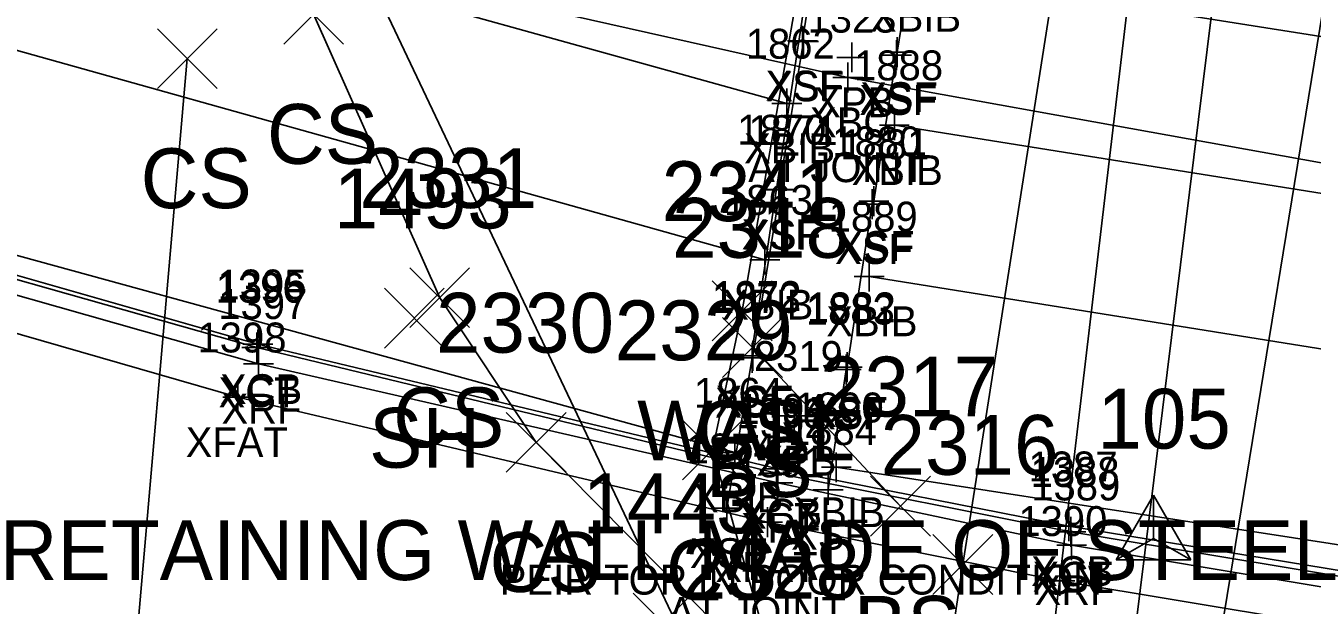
# Model space of a CAD drawing. Extents: x 1761340 to 1763889, y 696770 to 706023.
# Drawn here: x 1761614.72 to 1761657.73, y 700833.39 to 700852.76 of the extents above; entities that cross this region are included whole.
import ezdxf

# ---------------------------------------------------------------- set-up
doc = ezdxf.new("R2010")
doc.units = 0
for name, color, linetype in [('B_A', 7, 'Continuous'), ('B_C', 7, 'Continuous'), ('B_I', 7, 'Continuous'), ('B_TIC', 7, 'Continuous'), ('BB', 7, 'Continuous'), ('BDC', 7, 'Continuous'), ('BDEFAULT', 7, 'Continuous'), ('BELB', 7, 'Continuous'), ('BF', 7, 'Continuous'), ('BR', 7, 'Continuous'), ('C_I', 7, 'Continuous'), ('CPSM', 7, 'Continuous'), ('DCP', 7, 'Continuous'), ('L_A', 7, 'Continuous'), ('L_C', 7, 'Continuous'), ('L_I', 7, 'Continuous'), ('L_TIC', 7, 'Continuous'), ('LELB', 7, 'Continuous'), ('LW', 7, 'Continuous'), ('RDP', 7, 'Continuous')]:
    doc.layers.add(name, color=color, linetype=linetype)

msp = doc.modelspace()

# ---------------------------------------------------------------- linework, layer by layer
at = {"layer": 'B_TIC'}
for p, q in [((1761640.691, 700852.26), (1761640.767, 700852.26)), ((1761640.721, 700852.234), (1761640.796, 700852.234)), ((1761643.857, 700851.874), (1761643.933, 700851.874)), ((1761642.34, 700851.704), (1761642.416, 700851.704)), ((1761643.83, 700851.779), (1761643.905, 700851.779)), ((1761642.201, 700851.032), (1761642.277, 700851.032)), ((1761640.164, 700850.159), (1761640.24, 700850.159)), ((1761643.761, 700849.435), (1761643.836, 700849.435)), ((1761639.896, 700847.284), (1761639.971, 700847.284)), ((1761639.948, 700847.27), (1761640.024, 700847.27)), ((1761643.018, 700846.796), (1761643.093, 700846.796)), ((1761643.073, 700846.895), (1761643.148, 700846.895)), ((1761639.434, 700844.939), (1761639.509, 700844.939)), ((1761642.915, 700844.38), (1761642.991, 700844.38)), ((1761622.448, 700842.003), (1761622.523, 700842.003)), ((1761622.481, 700842.11), (1761622.556, 700842.11)), ((1761639.007, 700841.662), (1761639.083, 700841.662)), ((1761639.024, 700841.723), (1761639.1, 700841.723)), ((1761622.508, 700841.455), (1761622.583, 700841.455)), ((1761642.146, 700841.272), (1761642.221, 700841.272)), ((1761642.181, 700841.346), (1761642.257, 700841.346)), ((1761621.814, 700840.338), (1761621.89, 700840.338)), ((1761640.414, 700839.718), (1761640.489, 700839.718)), ((1761638.43, 700838.488), (1761638.505, 700838.488)), ((1761639.826, 700837.803), (1761639.901, 700837.803)), ((1761639.863, 700837.948), (1761639.938, 700837.948)), ((1761641.82, 700837.998), (1761641.896, 700837.998)), ((1761639.869, 700837.475), (1761639.945, 700837.475)), ((1761641.548, 700837.242), (1761641.624, 700837.242)), ((1761638.163, 700836.627), (1761638.238, 700836.627)), ((1761639.522, 700836.163), (1761639.598, 700836.163)), ((1761649.592, 700836.026), (1761649.667, 700836.026)), ((1761649.66, 700835.839), (1761649.736, 700835.839)), ((1761649.686, 700835.39), (1761649.762, 700835.39)), ((1761649.296, 700834.2), (1761649.371, 700834.2))]:
    msp.add_line(p, q, dxfattribs=at)
for points in [[(1761640.688, 700851.76), (1761640.688, 700852.76)], [(1761640.717, 700851.734), (1761640.717, 700852.734)], [(1761640.188, 700852.26), (1761641.188, 700852.26)], [(1761640.217, 700852.234), (1761641.217, 700852.234)], [(1761643.826, 700851.279), (1761643.826, 700852.279)], [(1761643.854, 700851.374), (1761643.854, 700852.374)], [(1761642.337, 700851.204), (1761642.337, 700852.204)], [(1761643.354, 700851.874), (1761644.354, 700851.874)], [(1761641.837, 700851.704), (1761642.837, 700851.704)], [(1761642.198, 700850.532), (1761642.198, 700851.532)], [(1761643.326, 700851.779), (1761644.326, 700851.779)], [(1761641.698, 700851.032), (1761642.698, 700851.032)], [(1761640.161, 700849.659), (1761640.161, 700850.659)], [(1761639.661, 700850.159), (1761640.661, 700850.159)], [(1761643.757, 700848.935), (1761643.757, 700849.935)], [(1761643.257, 700849.435), (1761644.257, 700849.435)], [(1761639.892, 700846.784), (1761639.892, 700847.784)], [(1761639.945, 700846.77), (1761639.945, 700847.77)], [(1761639.392, 700847.284), (1761640.392, 700847.284)], [(1761639.445, 700847.27), (1761640.445, 700847.27)], [(1761643.014, 700846.296), (1761643.014, 700847.296)], [(1761643.069, 700846.395), (1761643.069, 700847.395)], [(1761642.514, 700846.796), (1761643.514, 700846.796)], [(1761642.569, 700846.895), (1761643.569, 700846.895)], [(1761639.43, 700844.439), (1761639.43, 700845.439)], [(1761638.93, 700844.939), (1761639.93, 700844.939)], [(1761642.912, 700843.88), (1761642.912, 700844.88)], [(1761642.412, 700844.38), (1761643.412, 700844.38)], [(1761622.444, 700841.503), (1761622.444, 700842.503)], [(1761622.478, 700841.61), (1761622.478, 700842.61)], [(1761621.944, 700842.003), (1761622.944, 700842.003)], [(1761621.978, 700842.11), (1761622.978, 700842.11)], [(1761622.504, 700840.955), (1761622.504, 700841.955)], [(1761639.004, 700841.162), (1761639.004, 700842.162)], [(1761639.021, 700841.223), (1761639.021, 700842.223)], [(1761638.504, 700841.662), (1761639.504, 700841.662)], [(1761638.521, 700841.723), (1761639.521, 700841.723)], [(1761642.142, 700840.772), (1761642.142, 700841.772)], [(1761642.178, 700840.846), (1761642.178, 700841.846)], [(1761622.004, 700841.455), (1761623.004, 700841.455)], [(1761641.642, 700841.272), (1761642.642, 700841.272)], [(1761641.678, 700841.346), (1761642.678, 700841.346)], [(1761621.811, 700839.838), (1761621.811, 700840.838)], [(1761621.311, 700840.338), (1761622.311, 700840.338)], [(1761640.41, 700839.218), (1761640.41, 700840.218)], [(1761639.91, 700839.718), (1761640.91, 700839.718)], [(1761638.426, 700837.988), (1761638.426, 700838.988)], [(1761637.926, 700838.488), (1761638.926, 700838.488)], [(1761641.817, 700837.498), (1761641.817, 700838.498)], [(1761639.822, 700837.303), (1761639.822, 700838.303)], [(1761639.859, 700837.448), (1761639.859, 700838.448)], [(1761639.322, 700837.803), (1761640.322, 700837.803)], [(1761639.359, 700837.948), (1761640.359, 700837.948)], [(1761639.866, 700836.975), (1761639.866, 700837.975)], [(1761641.317, 700837.998), (1761642.317, 700837.998)], [(1761641.545, 700836.742), (1761641.545, 700837.742)], [(1761639.366, 700837.475), (1761640.366, 700837.475)], [(1761641.045, 700837.242), (1761642.045, 700837.242)], [(1761638.159, 700836.127), (1761638.159, 700837.127)], [(1761637.659, 700836.627), (1761638.659, 700836.627)], [(1761639.519, 700835.663), (1761639.519, 700836.663)], [(1761649.588, 700835.526), (1761649.588, 700836.526)], [(1761649.657, 700835.339), (1761649.657, 700836.339)], [(1761639.019, 700836.163), (1761640.019, 700836.163)], [(1761649.088, 700836.026), (1761650.088, 700836.026)], [(1761649.683, 700834.89), (1761649.683, 700835.89)], [(1761649.157, 700835.839), (1761650.157, 700835.839)], [(1761649.183, 700835.39), (1761650.183, 700835.39)], [(1761649.292, 700833.7), (1761649.292, 700834.7)], [(1761648.792, 700834.2), (1761649.792, 700834.2)]]:
    msp.add_lwpolyline(points, dxfattribs=at)
at = {"layer": 'BB'}
for points in [[(1761601.935, 700860.779), (1761640.161, 700850.159)], [(1761601.147, 700855.664), (1761639.43, 700844.939)], [(1761644.371, 700854.559), (1761682.392, 700848.561)], [(1761643.757, 700849.435), (1761681.627, 700843.391)], [(1761600.182, 700848.994), (1761638.426, 700838.488)], [(1761642.912, 700844.38), (1761681.017, 700838.268)], [(1761641.817, 700837.998), (1761679.884, 700832.117)]]:
    msp.add_lwpolyline(points, dxfattribs=at)
at = {"layer": 'BDC'}
for points in [[(1761724.868, 700826.95), (1761724.871, 700828.587), (1761705.949, 700829.474), (1761692.314, 700830.32), (1761682.204, 700831.236), (1761665.465, 700833.226), (1761649.657, 700835.839), (1761639.822, 700837.803), (1761622.444, 700842.003), (1761607.253, 700846.305), (1761598.594, 700848.947), (1761598.241, 700847.438)], [(1761725.044, 700828.858), (1761705.996, 700829.643), (1761692.291, 700830.53), (1761682.242, 700831.437), (1761665.497, 700833.418), (1761649.588, 700836.026), (1761639.859, 700837.948), (1761622.478, 700842.11), (1761607.258, 700846.457), (1761598.593, 700849.162)]]:
    msp.add_lwpolyline(points, dxfattribs=at)
at = {"layer": 'BDEFAULT'}
for points in [[(1761642.878, 700866.943), (1761641.572, 700857.817), (1761641.546, 700857.814), (1761640.688, 700852.26), (1761640.717, 700852.234), (1761639.892, 700847.284), (1761639.945, 700847.27), (1761639.021, 700841.723), (1761639.004, 700841.662), (1761638.159, 700836.627)], [(1761645.899, 700864.681), (1761644.76, 700857.46), (1761644.746, 700857.382), (1761643.854, 700851.874), (1761643.826, 700851.779), (1761643.069, 700846.895), (1761643.014, 700846.796), (1761642.178, 700841.346), (1761642.142, 700841.272), (1761641.545, 700837.242)]]:
    msp.add_lwpolyline(points, dxfattribs=at)
at = {"layer": 'BELB'}
msp.add_lwpolyline([(1761601.149, 700861.879), (1761622.312, 700855.499), (1761642.198, 700851.032), (1761664.959, 700846.932), (1761684.404, 700844.626), (1761702.463, 700842.89), (1761719.736, 700841.994), (1761727.361, 700840.892)], dxfattribs=at)
at = {"layer": 'BF'}
msp.add_lwpolyline([(1761724.868, 700826.95), (1761706.242, 700827.778), (1761692.328, 700828.536), (1761682.079, 700829.49), (1761665.583, 700831.495), (1761649.292, 700834.2), (1761639.519, 700836.163), (1761621.811, 700840.338), (1761606.756, 700844.682), (1761598.241, 700847.438)], dxfattribs=at)
at = {"layer": 'BR'}
msp.add_lwpolyline([(1761724.372, 700828.339), (1761706.015, 700828.859), (1761692.389, 700829.783), (1761682.17, 700830.837), (1761665.431, 700832.762), (1761649.683, 700835.39), (1761639.866, 700837.475), (1761622.504, 700841.455), (1761607.196, 700845.805), (1761599.069, 700848.455)], dxfattribs=at)
at = {"layer": 'CPSM'}
for p, q in [((1761651.166, 700834.901), (1761652.416, 700837.066)), ((1761653.666, 700834.901), (1761652.416, 700837.066)), ((1761652.416, 700835.623), (1761652.416, 700837.066)), ((1761651.166, 700834.901), (1761652.416, 700835.623)), ((1761652.416, 700835.623), (1761652.416, 700835.623)), ((1761652.416, 700835.623), (1761653.666, 700834.901)), ((1761651.166, 700834.901), (1761653.666, 700834.901))]:
    msp.add_line(p, q, dxfattribs=at)
at = {"layer": 'DCP'}
msp.add_lwpolyline([(1761640.818, 700823.61), (1761622.01, 700863.245)], dxfattribs=at)
at = {"layer": 'L_TIC'}
for points in [[(1761623.344, 700852.144), (1761625.344, 700854.144)], [(1761625.344, 700852.144), (1761623.344, 700854.144)], [(1761619.121, 700850.662), (1761621.121, 700852.662)], [(1761621.121, 700850.662), (1761619.121, 700852.662)], [(1761627.56, 700842.668), (1761629.56, 700844.668)], [(1761629.56, 700842.668), (1761627.56, 700844.668)], [(1761637.669, 700842.229), (1761639.669, 700844.229)], [(1761639.669, 700842.229), (1761637.669, 700844.229)], [(1761637.669, 700842.229), (1761639.669, 700844.229)], [(1761639.669, 700842.229), (1761637.669, 700844.229)], [(1761626.71, 700841.986), (1761628.71, 700843.986)], [(1761628.71, 700841.986), (1761626.71, 700843.986)], [(1761638.017, 700841.004), (1761640.017, 700843.004)], [(1761640.017, 700841.004), (1761638.017, 700843.004)], [(1761630.782, 700837.831), (1761632.782, 700839.831)], [(1761632.782, 700837.831), (1761630.782, 700839.831)], [(1761636.677, 700837.577), (1761638.677, 700839.577)], [(1761638.677, 700837.577), (1761636.677, 700839.577)], [(1761642.963, 700835.697), (1761644.963, 700837.697)], [(1761644.963, 700835.697), (1761642.963, 700837.697)], [(1761645.043, 700833.747), (1761647.043, 700835.747)], [(1761647.043, 700833.747), (1761645.043, 700835.747)], [(1761635.024, 700831.793), (1761637.024, 700833.793)], [(1761637.024, 700831.793), (1761635.024, 700833.793)]]:
    msp.add_lwpolyline(points, dxfattribs=at)
at = {"layer": 'LELB'}
for points in [[(1761650.668, 700568.581), (1761653.72, 700589.345), (1761656.228, 700611.846), (1761650.783, 700645.878), (1761646.693, 700682.268), (1761643.965, 700721.139), (1761646.185, 700763.151), (1761649.001, 700791.974), (1761651.08, 700826.684), (1761655.56, 700862.863), (1761665.437, 700900.351), (1761673.527, 700937.717), (1761682.384, 700964.347), (1761693.002, 701008.082), (1761690.127, 701015.338), (1761683.006, 701019.111)], [(1761647.361, 700568.693), (1761651.507, 700589.637), (1761652.179, 700611.172), (1761648.147, 700645.92), (1761644.284, 700683.035), (1761641.556, 700721.375), (1761643.749, 700763.66), (1761644.587, 700792.445), (1761648.472, 700827.402), (1761652.737, 700863.508), (1761659.58, 700901.674), (1761670.104, 700938.531), (1761679.505, 700964.488), (1761691.194, 701008.19), (1761682.174, 701016.504)], [(1761650.212, 700590.246), (1761648.805, 700610.457), (1761644.582, 700645.542), (1761640.712, 700682.502), (1761639.82, 700689.73), (1761639.14, 700693.979), (1761637.85, 700721.718), (1761639.717, 700763.338), (1761641.24, 700792.73), (1761643.277, 700816.475), (1761646.043, 700834.747), (1761651.107, 700867.028), (1761649.907, 700870.225), (1761650.052, 700873.461)], [(1761643.963, 700836.697), (1761639.017, 700842.004), (1761642.014, 700861.826), (1761646.028, 700861.397), (1761651.107, 700867.028)], [(1761639.915, 700830.601), (1761631.782, 700838.831), (1761628.56, 700843.668), (1761624.344, 700853.144), (1761608.772, 700864.631), (1761621.099, 700862.527), (1761628.557, 700864.432)], [(1761618.082, 700828.178), (1761620.121, 700851.662)], [(1761639.915, 700830.601), (1761637.677, 700838.577), (1761638.669, 700843.229)]]:
    msp.add_lwpolyline(points, dxfattribs=at)
at = {"layer": 'LW'}
msp.add_lwpolyline([(1761638.669, 700843.229), (1761642.163, 700863.358)], dxfattribs=at)
at = {"layer": 'RDP'}
msp.add_lwpolyline([(1761671.259, 700538.434), (1761661.644, 700574.622), (1761657.605, 700611.792), (1761653.176, 700645.742), (1761649.934, 700682.027), (1761646.901, 700721.235), (1761649.099, 700763.058), (1761651.354, 700791.608), (1761653.655, 700826.216), (1761659.48, 700861.884), (1761668.314, 700899.372), (1761676.768, 700936.595), (1761684.872, 700963.935), (1761695.512, 701007.432), (1761695.754, 701009.139), (1761702.957, 701038.717), (1761714.691, 701083.389), (1761730.248, 701133.725)], dxfattribs=at)

# ---------------------------------------------------------------- texts
at = {"layer": 'B_A'}
for s, p in [('XBIB', (1761642.942, 700852.559)), ('XSF', (1761639.448, 700850.26)), ('XSF', (1761639.477, 700850.234)), ('XPB', (1761641.073, 700849.704)), ('XSF', (1761642.586, 700849.779)), ('XSF', (1761642.613, 700849.874)), ('XBC', (1761640.934, 700849.032)), ('XBIB', (1761638.732, 700848.159)), ('XBIB', (1761642.328, 700847.435)), ('XSF', (1761638.652, 700845.284)), ('XSF', (1761638.705, 700845.27)), ('XSF', (1761641.774, 700844.796)), ('XSF', (1761641.829, 700844.895)), ('XBIB', (1761638.001, 700842.939)), ('XBIB', (1761641.483, 700842.38)), ('XCB', (1761621.214, 700840.11)), ('XCT', (1761621.165, 700840.003)), ('XSF', (1761637.764, 700839.662)), ('XSF', (1761637.78, 700839.723)), ('XRF', (1761621.264, 700839.455)), ('XSF', (1761640.902, 700839.272)), ('XSF', (1761640.938, 700839.346)), ('XFAT', (1761620.067, 700838.338)), ('XPB', (1761639.146, 700837.718)), ('XBIB', (1761636.997, 700836.488)), ('XCT', (1761638.543, 700835.803)), ('XCB', (1761638.595, 700835.948)), ('XBIB', (1761640.388, 700835.998)), ('XRF', (1761638.625, 700835.475)), ('XSF', (1761640.305, 700835.242)), ('XSF', (1761636.919, 700834.627)), ('XFAT', (1761637.775, 700834.163)), ('XCB', (1761648.325, 700834.026)), ('XCT', (1761648.377, 700833.839)), ('XRF', (1761648.443, 700833.39))]:
    msp.add_text(s, height=1, dxfattribs=at).set_placement(p)
at = {"layer": 'B_C'}
for s, p in [('AT JOINT', (1761638.871, 700847.532)), ('PEIR TOP IN POOR CONDITION', (1761630.565, 700833.742)), ('AT JOINT', (1761636.192, 700832.663))]:
    msp.add_text(s, height=1, dxfattribs=at).set_placement(p)
at = {"layer": 'B_I'}
for s, p in [('1323', (1761640.852, 700852.532)), ('1862', (1761638.791, 700851.659)), ('1888', (1761642.411, 700850.935)), ('1870', (1761638.503, 700848.784)), ('1871', (1761638.882, 700848.77)), ('1880', (1761641.68, 700848.395)), ('1881', (1761641.951, 700848.296)), ('1863', (1761638.06, 700846.439)), ('1889', (1761641.561, 700845.88)), ('1396', (1761621.07, 700843.503)), ('1395', (1761621.131, 700843.61)), ('1873', (1761637.658, 700843.162)), ('1872', (1761637.674, 700843.223)), ('1397', (1761621.158, 700842.955)), ('1883', (1761640.796, 700842.772)), ('1882', (1761640.831, 700842.846)), ('1398', (1761620.464, 700841.838)), ('2319', (1761639.06, 700841.218)), ('1864', (1761637.056, 700839.988)), ('1393', (1761638.476, 700839.303)), ('1394', (1761638.513, 700839.448)), ('1890', (1761640.427, 700839.498)), ('1392', (1761638.519, 700838.975)), ('1884', (1761640.199, 700838.742)), ('1874', (1761636.813, 700838.127)), ('1391', (1761638.456, 700837.663)), ('1387', (1761648.242, 700837.526)), ('1388', (1761648.31, 700837.339)), ('1389', (1761648.333, 700836.89)), ('1390', (1761647.902, 700835.7))]:
    msp.add_text(s, height=1, dxfattribs=at).set_placement(p)
at = {"layer": 'C_I'}
msp.add_text('105', height=2, dxfattribs=at).set_placement((1761650.542, 700838.623))
at = {"layer": 'L_A'}
for s, p in [('CS', (1761622.785, 700848.144)), ('CS', (1761618.562, 700846.662)), ('CS', (1761627.001, 700838.668)), ('WALL', (1761635.157, 700838.229)), ('CS', (1761637.11, 700838.229)), ('SH', (1761626.198, 700837.986)), ('BS', (1761637.458, 700837.004)), ('CS', (1761630.223, 700833.831)), ('CS', (1761636.118, 700833.577)), ('BS', (1761642.404, 700831.697))]:
    msp.add_text(s, height=2, dxfattribs=at).set_placement(p)
at = {"layer": 'L_C'}
msp.add_text('RETAINING WALL MADE OF STEEL', height=2, dxfattribs=at).set_placement((1761613.851, 700834.229))
at = {"layer": 'L_I'}
for s, p in [('2331', (1761625.867, 700846.668)), ('1493', (1761625.017, 700845.986)), ('2341', (1761635.976, 700846.229)), ('2341', (1761635.976, 700846.229)), ('2318', (1761636.325, 700845.004)), ('2330', (1761628.436, 700841.831)), ('2329', (1761634.409, 700841.577)), ('2317', (1761641.271, 700839.697)), ('2316', (1761643.295, 700837.747)), ('1443', (1761633.332, 700835.793)), ('2328', (1761636.656, 700833.601)), ('2328', (1761636.656, 700833.601))]:
    msp.add_text(s, height=2, dxfattribs=at).set_placement(p)

doc.saveas('drawing.dxf')
